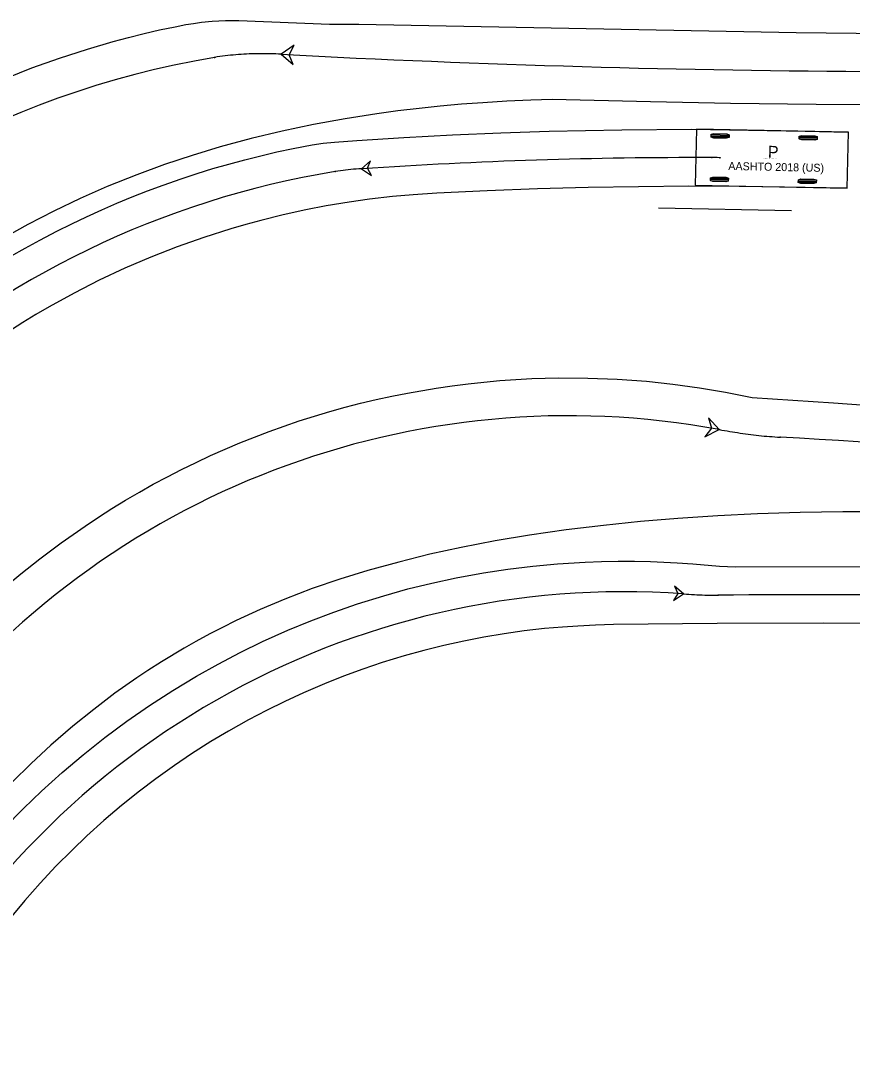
# Model space of a CAD drawing. Extents: x 2175591 to 2194071, y 76570 to 86955.
# Drawn here: x 2192986.5 to 2193090.5, y 86600.4 to 86728.8 of the extents above; entities that cross this region are included whole.
import ezdxf

# ---------------------------------------------------------------- set-up
doc = ezdxf.new("R2010")
doc.units = 0
doc.layers.add('C-UTIL-STRM-TEXT', color=7, linetype='Continuous')

msp = doc.modelspace()

# ---------------------------------------------------------------- linework, layer by layer
at = {"layer": 'C-UTIL-STRM-TEXT'}
for p, q in [((2193070.99, 86715.26), (2193070.85, 86708.26)), ((2193089.99, 86714.87), (2193070.99, 86715.26)), ((2193072.85, 86714.58), (2193075.1, 86714.53)), ((2193089.84, 86707.87), (2193089.99, 86714.87)), ((2193072.85, 86714.44), (2193075.1, 86714.39)), ((2193072.85, 86714.3), (2193075.1, 86714.25)), ((2193083.85, 86714.35), (2193086.1, 86714.31)), ((2193083.85, 86714.21), (2193086.1, 86714.17)), ((2193083.85, 86714.07), (2193086.1, 86714.03)), ((2193070.85, 86708.26), (2193089.84, 86707.87)), ((2193070.85, 86708.26), (2193070.85, 86708.26)), ((2193072.74, 86709.15), (2193074.99, 86709.1)), ((2193072.74, 86709), (2193074.99, 86708.96)), ((2193072.74, 86708.86), (2193074.99, 86708.82)), ((2193083.73, 86708.64), (2193085.98, 86708.59)), ((2193083.74, 86708.92), (2193085.99, 86708.87)), ((2193083.74, 86708.78), (2193085.99, 86708.73)), ((2193066.26, 86705.45), (2193082.87, 86705.11))]:
    msp.add_line(p, q, dxfattribs=at)
for points in [[(2192984.85, 86721.69), (2192987.95, 86722.91), (2192991.4, 86724.14), (2192994.89, 86725.27), (2192998.09, 86726.21), (2193000.02, 86726.72), (2193001.96, 86727.21), (2193003.91, 86727.66), (2193005.87, 86728.07), (2193007.18, 86728.33), (2193008.16, 86728.49), (2193009.15, 86728.62), (2193010.48, 86728.75), (2193012.14, 86728.84), (2193013.81, 86728.84), (2193025.13, 86728.39), (2193028.8, 86728.38), (2193083.45, 86727.35), (2193098.45, 86727.16)], [(2193019.09, 86724.63), (2193020.61, 86723.33), (2193020.09, 86724.57), (2193020.74, 86725.76), (2193019.09, 86724.63)], [(2193019.09, 86724.63), (2193018.76, 86724.64), (2193018.42, 86724.66), (2193018.09, 86724.67), (2193017.76, 86724.68), (2193017.42, 86724.69), (2193017.09, 86724.69), (2193016.76, 86724.7), (2193016.42, 86724.7), (2193016.09, 86724.69), (2193015.76, 86724.69), (2193015.42, 86724.68), (2193015.09, 86724.67), (2193014.76, 86724.65), (2193014.42, 86724.63), (2193014.09, 86724.61), (2193013.76, 86724.59), (2193013.43, 86724.56), (2193013.09, 86724.53), (2193012.76, 86724.5), (2193012.43, 86724.46), (2193012.1, 86724.42), (2193011.77, 86724.38), (2193011.44, 86724.33), (2193011.11, 86724.29), (2193010.78, 86724.23)], [(2193096.28, 86718.31), (2193085.95, 86718.36), (2193075.28, 86718.49), (2193065.28, 86718.68), (2193052.96, 86718.99), (2193050.29, 86718.9), (2193047.29, 86718.76), (2193044.3, 86718.57), (2193041.64, 86718.37), (2193038.99, 86718.13), (2193036.33, 86717.86), (2193033.69, 86717.54), (2193031.04, 86717.19), (2193027.09, 86716.57), (2193023.16, 86715.85), (2193019.24, 86715.03), (2193015.35, 86714.09), (2193011.49, 86713.05), (2193007.98, 86711.99), (2193004.51, 86710.83), (2193001.06, 86709.57), (2192997.35, 86708.08), (2192993.99, 86706.6), (2192990.68, 86705.03), (2192987.42, 86703.35), (2192984.22, 86701.57)], [(2192985.33, 86699.37), (2192987.12, 86700.4), (2192988.94, 86701.39), (2192991.08, 86702.51), (2192992.93, 86703.43), (2192994.79, 86704.32), (2192996.68, 86705.18), (2192998.57, 86706), (2193000.48, 86706.79), (2193002.41, 86707.55), (2193004.35, 86708.27), (2193006.62, 86709.07), (2193008.59, 86709.71), (2193010.56, 86710.33), (2193012.55, 86710.9), (2193014.55, 86711.44), (2193016.55, 86711.95), (2193018.57, 86712.42), (2193020.6, 86712.86), (2193022.99, 86713.32), (2193024.36, 86713.52), (2193025.75, 86713.65), (2193028.54, 86713.85), (2193034.44, 86714.21), (2193040.53, 86714.54), (2193046.57, 86714.8), (2193052.6, 86715), (2193061.66, 86715.2), (2193070.38, 86715.27), (2193084.6, 86715), (2193089.97, 86714.87), (2193089.82, 86707.87)], [(2193029.15, 86710.32), (2193030.4, 86709.49), (2193029.9, 86710.37), (2193030.28, 86711.31), (2193029.15, 86710.32)], [(2193073.92, 86711.7), (2193073.59, 86711.71), (2193073.25, 86711.71), (2193072.92, 86711.71)], [(2193029.15, 86710.32), (2193028.82, 86710.3), (2193028.49, 86710.27), (2193028.15, 86710.25), (2193027.82, 86710.21), (2193027.49, 86710.18), (2193027.16, 86710.14), (2193026.83, 86710.1), (2193026.5, 86710.06), (2193026.17, 86710.01), (2193025.84, 86709.96)], [(2193089.82, 86707.87), (2193081.99, 86708.03), (2193076.36, 86708.1), (2193070.06, 86708.12), (2193063.75, 86708.07), (2193057.45, 86707.97), (2193051.15, 86707.8), (2193044.85, 86707.57), (2193038.56, 86707.27), (2193035.61, 86707.07), (2193033.03, 86706.84), (2193030.15, 86706.5), (2193027.6, 86706.14), (2193024.73, 86705.66), (2193022.19, 86705.16), (2193019.35, 86704.54), (2193016.54, 86703.84), (2193014.68, 86703.34), (2193012.82, 86702.8), (2193009.45, 86701.73), (2193006.12, 86700.55), (2193002.83, 86699.26), (2192999.58, 86697.87), (2192996.37, 86696.37), (2192993.22, 86694.77), (2192990.12, 86693.06), (2192988.45, 86692.09), (2192986.8, 86691.09), (2192983.83, 86689.18)], [(2192984.29, 86657.75), (2192986.58, 86659.68), (2192988.92, 86661.56), (2192991.59, 86663.56), (2192994.59, 86665.66), (2192996.26, 86666.77), (2192997.94, 86667.84), (2192999.65, 86668.88), (2193001.38, 86669.89), (2193003.12, 86670.87), (2193004.88, 86671.82), (2193006.66, 86672.73), (2193008.46, 86673.61), (2193010.27, 86674.46), (2193012.09, 86675.26), (2193013.92, 86676.04), (2193015.76, 86676.78), (2193017.62, 86677.48), (2193019.49, 86678.16), (2193021.37, 86678.79), (2193023.27, 86679.4), (2193025.18, 86679.97), (2193027.09, 86680.5), (2193029.02, 86681), (2193030.97, 86681.46), (2193032.92, 86681.89), (2193034.88, 86682.28), (2193038.49, 86682.9), (2193040.47, 86683.19), (2193042.46, 86683.44), (2193044.45, 86683.66), (2193046.44, 86683.84), (2193048.43, 86683.98), (2193050.43, 86684.08), (2193053.76, 86684.17), (2193057.43, 86684.16), (2193061.09, 86684.01), (2193064.75, 86683.75), (2193068.06, 86683.39), (2193071.37, 86682.94), (2193074.65, 86682.39), (2193077.96, 86681.72), (2193088.15, 86681.05), (2193096.13, 86680.47)], [(2193073.85, 86677.72), (2193072.51, 86679.2), (2193072.87, 86677.9), (2193072.07, 86676.81), (2193073.85, 86677.72)], [(2193073.85, 86677.72), (2193074.18, 86677.66), (2193074.51, 86677.6), (2193074.84, 86677.54), (2193075.16, 86677.49), (2193075.49, 86677.43), (2193075.82, 86677.38), (2193076.15, 86677.33), (2193076.48, 86677.28), (2193076.81, 86677.23), (2193077.14, 86677.18), (2193077.47, 86677.14), (2193077.8, 86677.09), (2193078.13, 86677.05), (2193078.46, 86677.02), (2193078.79, 86676.98), (2193079.13, 86676.94), (2193079.46, 86676.91), (2193079.79, 86676.88), (2193080.12, 86676.85), (2193080.45, 86676.83), (2193080.79, 86676.8), (2193081.12, 86676.78), (2193081.45, 86676.76)], [(2193094.97, 86667.45), (2193089.31, 86667.43), (2193083.98, 86667.34), (2193078.65, 86667.17), (2193073.66, 86666.93), (2193068.67, 86666.6), (2193064.02, 86666.21), (2193059.37, 86665.74), (2193054.74, 86665.17), (2193050.12, 86664.51), (2193045.85, 86663.79), (2193041.6, 86662.97), (2193037.69, 86662.12), (2193033.81, 86661.16), (2193029.95, 86660.1), (2193026.45, 86659.02), (2193022.98, 86657.83), (2193019.55, 86656.52), (2193016.48, 86655.23), (2193013.46, 86653.83), (2193011.67, 86652.94), (2193010.19, 86652.17), (2193008.43, 86651.22), (2193006.98, 86650.39), (2193004.13, 86648.67), (2193002.44, 86647.59), (2193001.06, 86646.67), (2192998.33, 86644.75), (2192995.67, 86642.74), (2192993.08, 86640.65), (2192990.3, 86638.25), (2192987.85, 86635.99), (2192985.47, 86633.66)], [(2192984.5, 86627.88), (2192986.91, 86630.35), (2192989.15, 86632.51), (2192991.71, 86634.83), (2192994.34, 86637.06), (2192997.05, 86639.21), (2192999.82, 86641.27), (2193002.65, 86643.24), (2193005.55, 86645.11), (2193008.51, 86646.89), (2193011.22, 86648.41), (2193013.98, 86649.85), (2193016.77, 86651.21), (2193019.92, 86652.63), (2193022.8, 86653.81), (2193025.7, 86654.91), (2193028.64, 86655.93), (2193031.94, 86656.95), (2193034.93, 86657.79), (2193037.95, 86658.53), (2193040.99, 86659.19), (2193044.38, 86659.81), (2193047.45, 86660.28), (2193050.54, 86660.66), (2193053.63, 86660.95), (2193057.08, 86661.16), (2193059.15, 86661.24), (2193061.21, 86661.27), (2193063.25, 86661.27), (2193065.26, 86661.22), (2193068.58, 86661.07), (2193070.56, 86660.93), (2193073.89, 86660.64), (2193075.89, 86660.56), (2193091.9, 86660.58)], [(2193069.4, 86657.17), (2193068.28, 86658.16), (2193068.66, 86657.22), (2193068.15, 86656.34), (2193069.4, 86657.17)], [(2193069.4, 86657.17), (2193069.74, 86657.15), (2193070.07, 86657.12), (2193070.4, 86657.1), (2193070.74, 86657.08), (2193071.07, 86657.07), (2193071.4, 86657.05), (2193071.73, 86657.04), (2193072.07, 86657.03), (2193072.4, 86657.02), (2193072.73, 86657.02), (2193073.07, 86657.01), (2193073.4, 86657.01), (2193073.73, 86657.02)], [(2193098.52, 86653.49), (2193086.9, 86653.53), (2193073.61, 86653.48), (2193060.65, 86653.33), (2193058.4, 86653.26), (2193056.17, 86653.16), (2193054.26, 86653.03), (2193052.03, 86652.83), (2193049.49, 86652.54), (2193046.96, 86652.18), (2193044.43, 86651.76), (2193041.93, 86651.27), (2193039.43, 86650.72), (2193036.95, 86650.1), (2193034.48, 86649.42), (2193031.73, 86648.58), (2193029.31, 86647.76), (2193026.91, 86646.88), (2193024.53, 86645.94), (2193021.89, 86644.81), (2193019.56, 86643.74), (2193017.27, 86642.61), (2193015.01, 86641.43), (2193012.5, 86640.02), (2193010.3, 86638.71), (2193007.88, 86637.17), (2193005.76, 86635.74), (2193003.42, 86634.06), (2193001.38, 86632.52), (2192999.14, 86630.72), (2192996.95, 86628.85), (2192994.81, 86626.93), (2192992.96, 86625.16), (2192990.94, 86623.12), (2192988.97, 86621.02), (2192987.07, 86618.86), (2192985.43, 86616.9)]]:
    msp.add_lwpolyline(points, dxfattribs=at)
for points in [[(2193019.09, 86724.63), (2193020.61, 86723.33), (2193020.09, 86724.57), (2193020.74, 86725.76)], [(2193072.85, 86714.27), (2193072.86, 86714.62), (2193073.17, 86714.72), (2193074.79, 86714.68), (2193075.1, 86714.57), (2193075.1, 86714.22), (2193074.78, 86714.12), (2193073.16, 86714.15)], [(2193083.85, 86714.04), (2193083.85, 86714.39), (2193084.17, 86714.49), (2193085.79, 86714.45), (2193086.1, 86714.34), (2193086.1, 86713.99), (2193085.78, 86713.89), (2193084.16, 86713.93)], [(2193029.15, 86710.32), (2193030.4, 86709.49), (2193029.9, 86710.37), (2193030.28, 86711.31)], [(2193072.74, 86708.83), (2193072.74, 86709.18), (2193073.06, 86709.28), (2193074.68, 86709.25), (2193074.99, 86709.13), (2193074.98, 86708.78), (2193074.67, 86708.68), (2193073.05, 86708.72)], [(2193083.73, 86708.6), (2193083.74, 86708.95), (2193084.06, 86709.05), (2193085.68, 86709.02), (2193085.99, 86708.91), (2193085.98, 86708.55), (2193085.67, 86708.46), (2193084.05, 86708.49)], [(2193073.85, 86677.72), (2193072.51, 86679.2), (2193072.87, 86677.9), (2193072.07, 86676.81)], [(2193069.4, 86657.17), (2193068.28, 86658.16), (2193068.66, 86657.22), (2193068.15, 86656.34)]]:
    msp.add_lwpolyline(points, close=True, dxfattribs=at)
for centre in [(2193010.78, 86724.23), (2193010.78, 86724.23), (2193019.09, 86724.63), (2193019.09, 86724.63), (2193072.92, 86711.71), (2193072.92, 86711.71), (2193073.92, 86711.7), (2193025.84, 86709.96), (2193025.84, 86709.96), (2193029.15, 86710.32), (2193029.15, 86710.32), (2193073.85, 86677.72), (2193073.85, 86677.72), (2193081.45, 86676.76), (2193081.45, 86676.76), (2193069.4, 86657.17), (2193069.4, 86657.17), (2193073.73, 86657.02), (2193073.73, 86657.02)]:
    msp.add_circle(centre, 0.0417, dxfattribs=at)
for centre, radius, start, end in [((2193029.49, 86612.53), 113.26, 99.5095, 179.4119), ((2193100.89, 88266.51), 1544.05, 266.96321, 269.75846), ((2193071.21, 86076.22), 635.49, 89.84567, 93.79462), ((2193044.16, 86598.37), 113.08, 99.323, 164.5442), ((2193055.05, 86576.23), 103.21, 79.504, 142.3503), ((2193030.16, 85731.9), 946.25, 82.15558, 86.89267), ((2193061.98, 86554.68), 102.76, 85.8586, 153.6088), ((2193086.58, 84967.27), 1689.8, 88.36985, 90.43544)]:
    msp.add_arc(centre, radius, start, end, dxfattribs=at)

# ---------------------------------------------------------------- texts
for s, height, p in [('P', 1.5, (2193079.92, 86711.69)), ('AASHTO 2018 (US)', 1, (2193074.98, 86710.17)), ('(c) 2024 Transoft Solutions, Inc. All rights reserved.', 0.06, (2193079.19, 86711.56))]:
    msp.add_text(s, height=height, rotation=358.8104, dxfattribs=at).set_placement(p)

doc.saveas('drawing.dxf')
